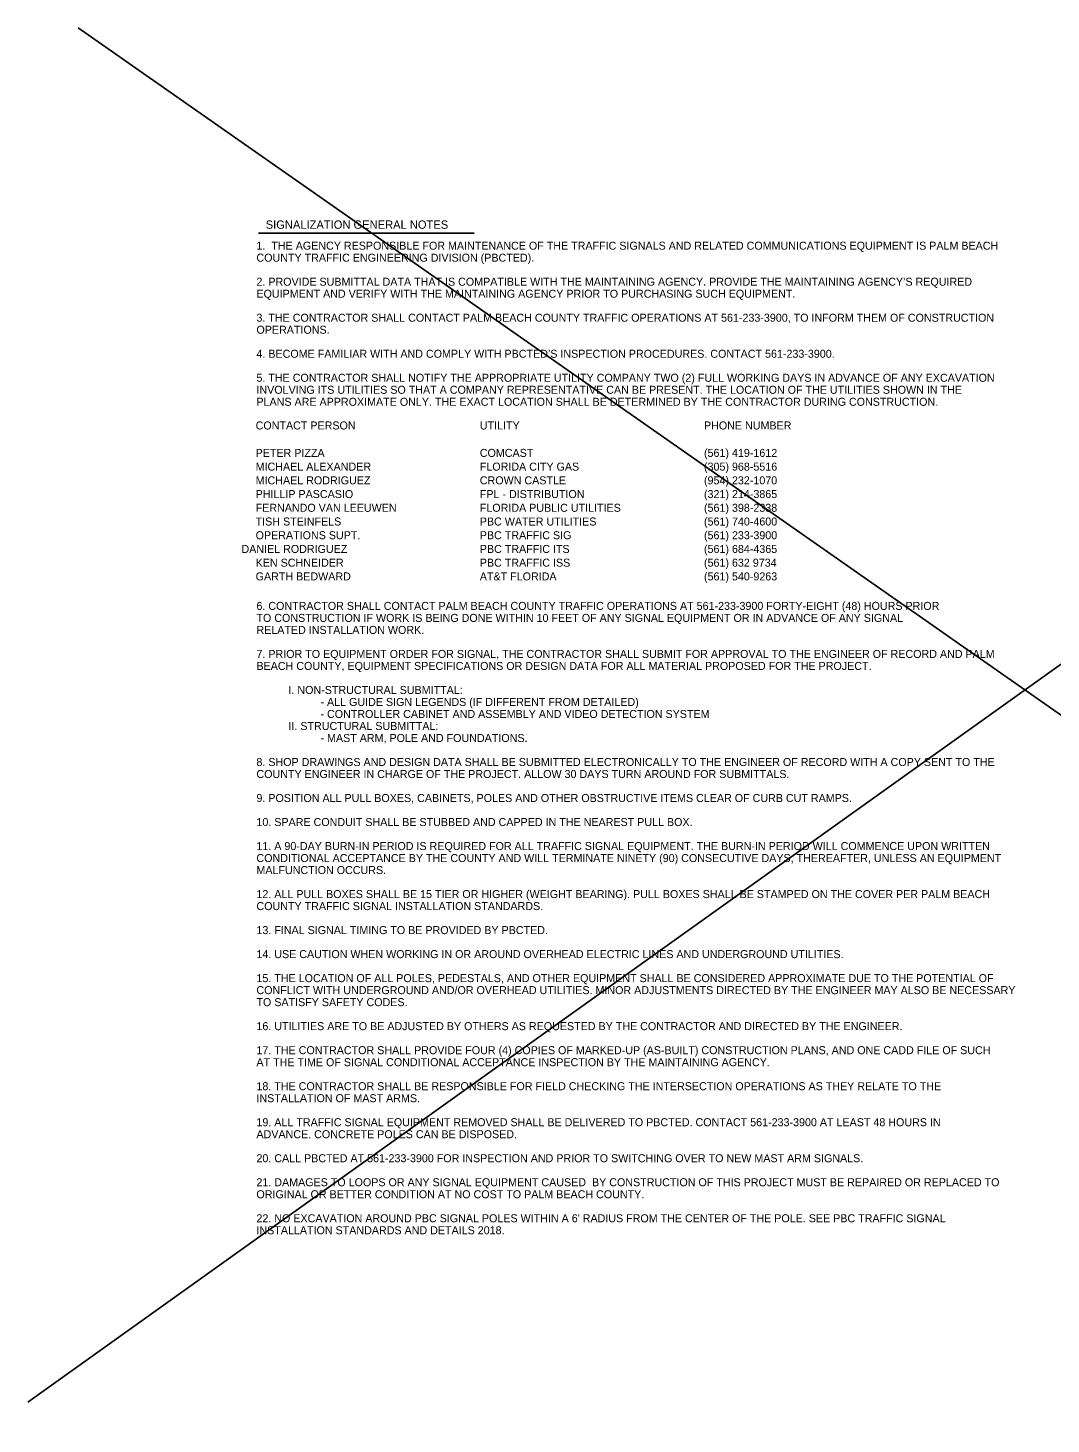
# Model space of a CAD drawing. Extents: x -1.6 to 33.4, y -12.7 to 10.9.
# Drawn here: x -1.57 to 7.37, y -1.35 to 10.86 of the extents above; entities that cross this region are included whole.
import ezdxf

# ---------------------------------------------------------------- set-up
doc = ezdxf.new("R2010")
doc.units = 0
doc.layers.add('NonPlottingEle_dp', color=7, linetype='Continuous')

msp = doc.modelspace()

# ---------------------------------------------------------------- linework, layer by layer
at = {"layer": 'NonPlottingEle_dp'}
for p, q in [((-1.131, 10.856), (16.32, -1.353)), ((15.056, 10.719), (-1.571, -1.16)), ((0.445, 9.062), (1.861, 9.062)), ((0.445, 9.062), (2.332, 9.062))]:
    msp.add_line(p, q, dxfattribs=at)

# ---------------------------------------------------------------- texts
for s, height, p in [('SIGNALIZATION GENERAL NOTES', 0.07279, (0.508, 9.1)), ('1.  THE AGENCY RESPONSIBLE FOR MAINTENANCE OF THE TRAFFIC SIGNALS AND RELATED COMMUNICATIONS EQUIPMENT IS PALM BEACH ', 0.07, (0.427, 8.917)), ('COUNTY TRAFFIC ENGINEERING DIVISION (PBCTED).', 0.07, (0.427, 8.812)), ('2. PROVIDE SUBMITTAL DATA THAT IS COMPATIBLE WITH THE MAINTAINING AGENCY. PROVIDE THE MAINTAINING AGENCY’S REQUIRED ', 0.07, (0.427, 8.602)), ('EQUIPMENT AND VERIFY WITH THE MAINTAINING AGENCY PRIOR TO PURCHASING SUCH EQUIPMENT.', 0.07, (0.427, 8.497)), ('3. THE CONTRACTOR SHALL CONTACT PALM BEACH COUNTY TRAFFIC OPERATIONS AT 561-233-3900, TO INFORM THEM OF CONSTRUCTION ', 0.07, (0.427, 8.287)), ('OPERATIONS.', 0.07, (0.427, 8.182)), ('4. BECOME FAMILIAR WITH AND COMPLY WITH PBCTED’S INSPECTION PROCEDURES. CONTACT 561-233-3900.', 0.07, (0.427, 7.972)), ('5. THE CONTRACTOR SHALL NOTIFY THE APPROPRIATE UTILITY COMPANY TWO (2) FULL WORKING DAYS IN ADVANCE OF ANY EXCAVATION ', 0.07, (0.427, 7.762)), ('INVOLVING ITS UTILITIES SO THAT A COMPANY REPRESENTATIVE CAN BE PRESENT. THE LOCATION OF THE UTILITIES SHOWN IN THE ', 0.07, (0.427, 7.657)), ('PLANS ARE APPROXIMATE ONLY. THE EXACT LOCATION SHALL BE DETERMINED BY THE CONTRACTOR DURING CONSTRUCTION.', 0.07, (0.427, 7.552)), ('CONTACT PERSON', 0.07, (0.42, 7.345)), ('UTILITY', 0.07, (2.38, 7.345)), ('PHONE NUMBER', 0.07, (4.34, 7.345)), ('PETER PIZZA', 0.07, (0.42, 7.105)), ('COMCAST', 0.07, (2.38, 7.105)), ('(561) 419-1612', 0.07, (4.34, 7.105)), ('MICHAEL ALEXANDER', 0.07, (0.42, 6.985)), ('FLORIDA CITY GAS', 0.07, (2.38, 6.985)), ('(305) 968-5516', 0.07, (4.34, 6.985)), ('MICHAEL RODRIGUEZ', 0.07, (0.42, 6.865)), ('CROWN CASTLE', 0.07, (2.38, 6.865)), ('(954) 232-1070', 0.07, (4.34, 6.865)), ('PHILLIP PASCASIO', 0.07, (0.42, 6.745)), ('FPL - DISTRIBUTION', 0.07, (2.38, 6.745)), ('(321) 214-3865', 0.07, (4.34, 6.745)), ('FERNANDO VAN LEEUWEN', 0.07, (0.42, 6.625)), ('FLORIDA PUBLIC UTILITIES', 0.07, (2.38, 6.625)), ('(561) 398-2338', 0.07, (4.34, 6.625)), ('TISH STEINFELS', 0.07, (0.42, 6.505)), ('PBC WATER UTILITIES', 0.07, (2.38, 6.505)), ('(561) 740-4600', 0.07, (4.34, 6.505)), ('OPERATIONS SUPT. ', 0.07, (0.42, 6.385)), ('PBC TRAFFIC SIG               ', 0.07, (2.38, 6.385)), ('(561) 233-3900', 0.07, (4.34, 6.385)), ('      DANIEL RODRIGUEZ', 0.07, (0.14, 6.265)), ('PBC TRAFFIC ITS', 0.07, (2.38, 6.265)), ('(561) 684-4365', 0.07, (4.34, 6.265)), ('KEN SCHNEIDER', 0.07, (0.42, 6.145)), ('PBC TRAFFIC ISS               ', 0.07, (2.38, 6.145)), ('(561) 632 9734', 0.07, (4.34, 6.145)), ('GARTH BEDWARD', 0.07, (0.42, 6.025)), ('AT&T FLORIDA', 0.07, (2.38, 6.025)), ('(561) 540-9263', 0.07, (4.34, 6.025)), ('6. CONTRACTOR SHALL CONTACT PALM BEACH COUNTY TRAFFIC OPERATIONS AT 561-233-3900 FORTY-EIGHT (48) HOURS PRIOR', 0.07, (0.427, 5.767)), ('TO CONSTRUCTION IF WORK IS BEING DONE WITHIN 10 FEET OF ANY SIGNAL EQUIPMENT OR IN ADVANCE OF ANY SIGNAL', 0.07, (0.427, 5.662)), ('RELATED INSTALLATION WORK.', 0.07, (0.427, 5.557)), ('7. PRIOR TO EQUIPMENT ORDER FOR SIGNAL, THE CONTRACTOR SHALL SUBMIT FOR APPROVAL TO THE ENGINEER OF RECORD AND PALM ', 0.07, (0.427, 5.347)), ('BEACH COUNTY, EQUIPMENT SPECIFICATIONS OR DESIGN DATA FOR ALL MATERIAL PROPOSED FOR THE PROJECT.', 0.07, (0.427, 5.242)), ('I. NON-STRUCTURAL SUBMITTAL: ', 0.07, (0.707, 5.032)), ('- ALL GUIDE SIGN LEGENDS (IF DIFFERENT FROM DETAILED)', 0.07, (0.987, 4.927)), ('- CONTROLLER CABINET AND ASSEMBLY AND VIDEO DETECTION SYSTEM', 0.07, (0.987, 4.822)), ('II. STRUCTURAL SUBMITTAL: ', 0.07, (0.707, 4.717)), ('- MAST ARM, POLE AND FOUNDATIONS.', 0.07, (0.987, 4.612)), ('8. SHOP DRAWINGS AND DESIGN DATA SHALL BE SUBMITTED ELECTRONICALLY TO THE ENGINEER OF RECORD WITH A COPY SENT TO THE ', 0.07, (0.427, 4.402)), ('COUNTY ENGINEER IN CHARGE OF THE PROJECT. ALLOW 30 DAYS TURN AROUND FOR SUBMITTALS.', 0.07, (0.427, 4.297)), ('9. POSITION ALL PULL BOXES, CABINETS, POLES AND OTHER OBSTRUCTIVE ITEMS CLEAR OF CURB CUT RAMPS.', 0.07, (0.427, 4.087)), ('10. SPARE CONDUIT SHALL BE STUBBED AND CAPPED IN THE NEAREST PULL BOX.', 0.07, (0.427, 3.877)), ('11. A 90-DAY BURN-IN PERIOD IS REQUIRED FOR ALL TRAFFIC SIGNAL EQUIPMENT. THE BURN-IN PERIOD WILL COMMENCE UPON WRITTEN ', 0.07, (0.427, 3.667)), ('CONDITIONAL ACCEPTANCE BY THE COUNTY AND WILL TERMINATE NINETY (90) CONSECUTIVE DAYS, THEREAFTER, UNLESS AN EQUIPMENT ', 0.07, (0.427, 3.562)), ('MALFUNCTION OCCURS.', 0.07, (0.427, 3.457)), ('12. ALL PULL BOXES SHALL BE 15 TIER OR HIGHER (WEIGHT BEARING). PULL BOXES SHALL BE STAMPED ON THE COVER PER PALM BEACH ', 0.07, (0.427, 3.247)), ('COUNTY TRAFFIC SIGNAL INSTALLATION STANDARDS.', 0.07, (0.427, 3.142)), ('13. FINAL SIGNAL TIMING TO BE PROVIDED BY PBCTED.', 0.07, (0.427, 2.932)), ('14. USE CAUTION WHEN WORKING IN OR AROUND OVERHEAD ELECTRIC LINES AND UNDERGROUND UTILITIES.', 0.07, (0.427, 2.722)), ('15. THE LOCATION OF ALL POLES, PEDESTALS, AND OTHER EQUIPMENT SHALL BE CONSIDERED APPROXIMATE DUE TO THE POTENTIAL OF ', 0.07, (0.427, 2.512)), ('CONFLICT WITH UNDERGROUND AND/OR OVERHEAD UTILITIES. MINOR ADJUSTMENTS DIRECTED BY THE ENGINEER MAY ALSO BE NECESSARY ', 0.07, (0.427, 2.407)), ('TO SATISFY SAFETY CODES.', 0.07, (0.427, 2.302)), ('16. UTILITIES ARE TO BE ADJUSTED BY OTHERS AS REQUESTED BY THE CONTRACTOR AND DIRECTED BY THE ENGINEER.', 0.07, (0.427, 2.092)), ('17. THE CONTRACTOR SHALL PROVIDE FOUR (4) COPIES OF MARKED-UP (AS-BUILT) CONSTRUCTION PLANS, AND ONE CADD FILE OF SUCH ', 0.07, (0.427, 1.882)), ('AT THE TIME OF SIGNAL CONDITIONAL ACCEPTANCE INSPECTION BY THE MAINTAINING AGENCY.', 0.07, (0.427, 1.777)), ('18. THE CONTRACTOR SHALL BE RESPONSIBLE FOR FIELD CHECKING THE INTERSECTION OPERATIONS AS THEY RELATE TO THE ', 0.07, (0.427, 1.567)), ('INSTALLATION OF MAST ARMS.', 0.07, (0.427, 1.462)), ('19. ALL TRAFFIC SIGNAL EQUIPMENT REMOVED SHALL BE DELIVERED TO PBCTED. CONTACT 561-233-3900 AT LEAST 48 HOURS IN ', 0.07, (0.427, 1.252)), ('ADVANCE. CONCRETE POLES CAN BE DISPOSED.', 0.07, (0.427, 1.147)), ('20. CALL PBCTED AT 561-233-3900 FOR INSPECTION AND PRIOR TO SWITCHING OVER TO NEW MAST ARM SIGNALS.', 0.07, (0.427, 0.937)), ('21. DAMAGES TO LOOPS OR ANY SIGNAL EQUIPMENT CAUSED  BY CONSTRUCTION OF THIS PROJECT MUST BE REPAIRED OR REPLACED TO ', 0.07, (0.427, 0.727)), ('ORIGINAL OR BETTER CONDITION AT NO COST TO PALM BEACH COUNTY.', 0.07, (0.427, 0.622)), ("22. NO EXCAVATION AROUND PBC SIGNAL POLES WITHIN A 6' RADIUS FROM THE CENTER OF THE POLE. SEE PBC TRAFFIC SIGNAL ", 0.07, (0.427, 0.412)), ('INSTALLATION STANDARDS AND DETAILS 2018.', 0.07, (0.427, 0.307))]:
    msp.add_text(s, height=height, dxfattribs=at).set_placement(p)

doc.saveas('drawing.dxf')
